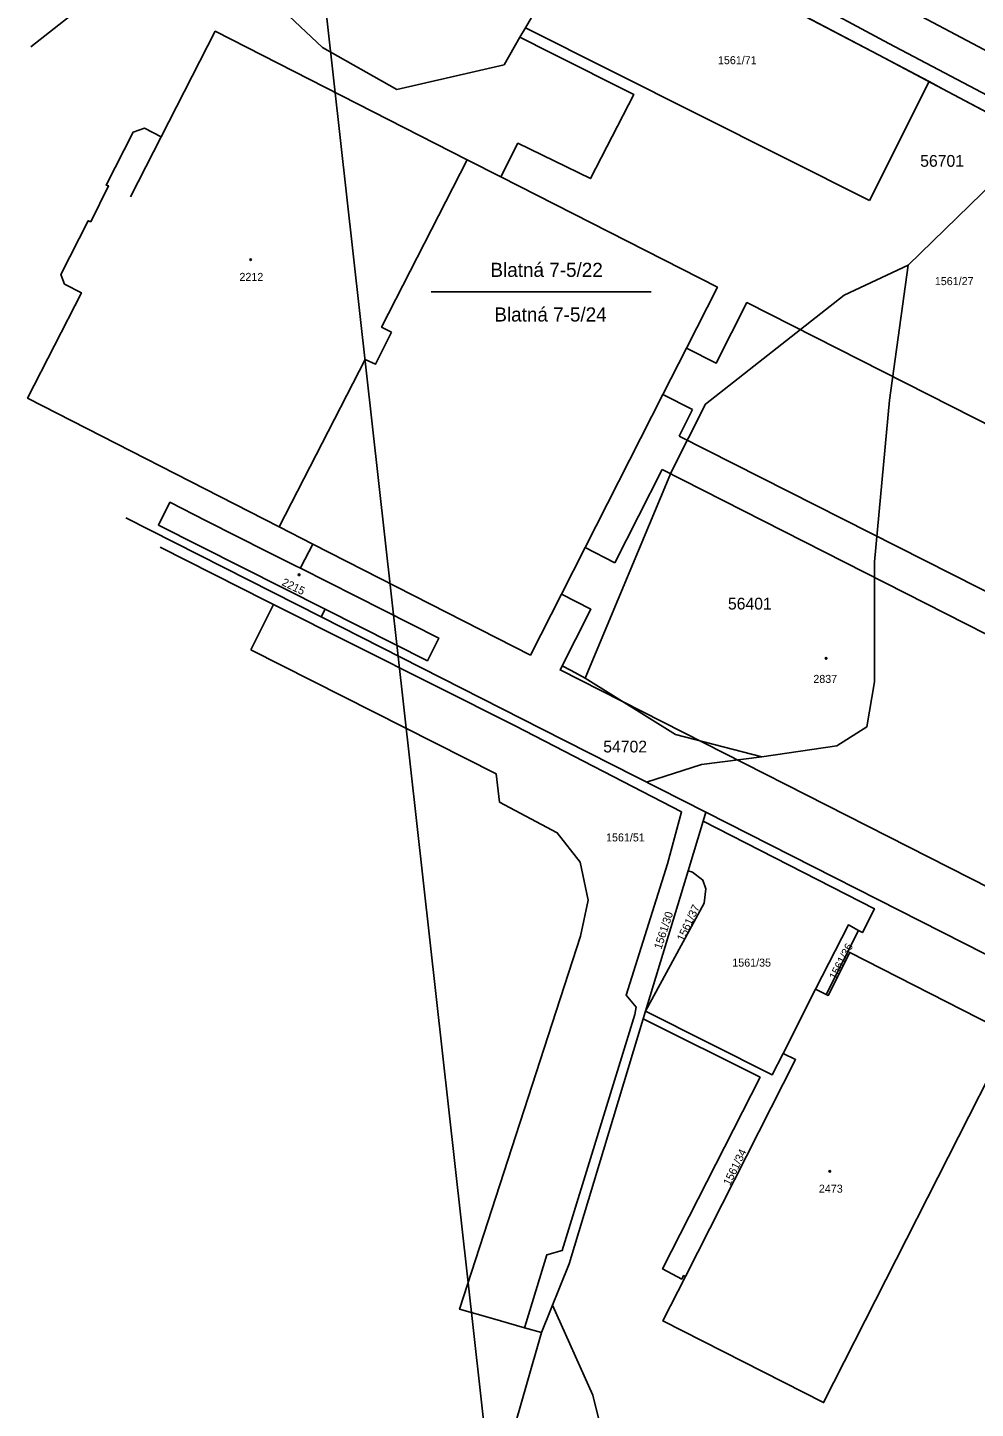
# Model space of a CAD drawing. Extents: x -794765 to -785424, y -1118958 to -1108731.
# Drawn here: x -792861.7 to -792660.4, y -1110737.1 to -1110443.9 of the extents above; entities that cross this region are included whole.
import ezdxf

# ---------------------------------------------------------------- set-up
doc = ezdxf.new("R2010")
doc.units = 0
for name, color, linetype in [('Level 71', 7, 'Continuous'), ('Level 75', 7, 'Continuous'), ('Level 76', 7, 'Continuous'), ('Level 77', 7, 'Continuous'), ('Level 79', 7, 'Continuous'), ('Level 81', 7, 'Continuous'), ('Vrstva 1', 7, 'Continuous')]:
    doc.layers.add(name, color=color, linetype=linetype)

msp = doc.modelspace()

# ---------------------------------------------------------------- linework, layer by layer
at = {"layer": 'Level 71'}
msp.add_lwpolyline([(-792522.06, -1110204.41), (-792422.02, -1111099.6), (-792720.93, -1111133), (-792820.96, -1110237.81)], close=True, dxfattribs=at)
at = {"layer": 'Level 75'}
for p, q in [((-792756.01, -1110443.91), (-792741.07, -1110418.09)), ((-792741.07, -1110418.09), (-792681.03, -1110449.67)), ((-792827.45, -1110421.43), (-792861.09, -1110447.98)), ((-792757.16, -1110445.89), (-792756.01, -1110443.91)), ((-792682.88, -1110480.58), (-792756.01, -1110443.91)), ((-792681.03, -1110449.67), (-792670.27, -1110455.33)), ((-792670.27, -1110455.33), (-792682.88, -1110480.58)), ((-792840.87, -1110547.97), (-792799.39, -1110569.04)), ((-792814.36, -1110576.02), (-792809.5, -1110566.39)), ((-792799.39, -1110569.04), (-792798.52, -1110567.4)), ((-792717.66, -1110610.53), (-792718.24, -1110612.44)), ((-792717.66, -1110610.53), (-792591.1, -1110674.8)), ((-792721.42, -1110622.95), (-792718.24, -1110612.44)), ((-792730.46, -1110652.76), (-792721.42, -1110622.95)), ((-792685.22, -1110635.61), (-792692.14, -1110649.21)), ((-792701.25, -1110661.74), (-792694.38, -1110648.11)), ((-792694.38, -1110648.11), (-792692.14, -1110649.21)), ((-792730.96, -1110654.38), (-792730.46, -1110652.76)), ((-792756.17, -1110720.02), (-792752.56, -1110721.04)), ((-792752.56, -1110721.04), (-792776.5, -1110804.34))]:
    msp.add_line(p, q, dxfattribs=at)
for points in [[(-792827.45, -1110421.43), (-792799.1, -1110448.12), (-792783.32, -1110457.02), (-792760.54, -1110451.74), (-792757.16, -1110445.89)], [(-792761.23, -1110475.55), (-792768.36, -1110471.92), (-792821.87, -1110444.63), (-792833.35, -1110467.07), (-792836.92, -1110465.24), (-792839.29, -1110466.05), (-792845.03, -1110477.35), (-792844.59, -1110477.44), (-792848.33, -1110485.09), (-792848.86, -1110484.89), (-792854.67, -1110496.33), (-792853.9, -1110498.34), (-792850.3, -1110500.18), (-792861.74, -1110522.54), (-792808.28, -1110549.91), (-792801.15, -1110553.55)], [(-792761.23, -1110475.55), (-792757.59, -1110468.44), (-792742.2, -1110475.94), (-792732.96, -1110458.09), (-792750.58, -1110449.21), (-792757.16, -1110445.89)], [(-792617.47, -1110483.28), (-792667.41, -1110456.84), (-792670.27, -1110455.33)], [(-792721.79, -1110511.93), (-792715.21, -1110499), (-792761.23, -1110475.55)], [(-792721.79, -1110511.93), (-792715.49, -1110515.15), (-792708.94, -1110502.27), (-792617.55, -1110548.61), (-792617.98, -1110549.46), (-792615.07, -1110550.92), (-792617.03, -1110554.92), (-792619.99, -1110553.41), (-792631.85, -1110576.75), (-792629.58, -1110577.89), (-792633.4, -1110585.25), (-792635.6, -1110584.14), (-792657.23, -1110626.73), (-792748.62, -1110580.29), (-792742.08, -1110567.4), (-792748.36, -1110564.21)], [(-792748.36, -1110564.21), (-792743.32, -1110554.29), (-792726.81, -1110521.82), (-792721.79, -1110511.93)], [(-792803.79, -1110558.7), (-792804.71, -1110558.23), (-792810.76, -1110555.18), (-792823.8, -1110548.59), (-792831.53, -1110544.69), (-792833.96, -1110549.51), (-792798.52, -1110567.4)], [(-792803.79, -1110558.7), (-792803.68, -1110558.49), (-792801.15, -1110553.55)], [(-792801.15, -1110553.55), (-792754.94, -1110577.15), (-792748.36, -1110564.21)], [(-792833.61, -1110554.24), (-792810.9, -1110565.68), (-792809.5, -1110566.39)], [(-792798.52, -1110567.4), (-792776.83, -1110578.34), (-792774.4, -1110573.53), (-792803.79, -1110558.7)], [(-792809.5, -1110566.39), (-792758.18, -1110592.2), (-792722.84, -1110610.45), (-792725.84, -1110621.49), (-792734.61, -1110649.36), (-792732.48, -1110651.94), (-792732.74, -1110653.49), (-792748.18, -1110703.64), (-792751.42, -1110704.51), (-792755.84, -1110718.93), (-792756.17, -1110720.02)], [(-792799.39, -1110569.04), (-792752.45, -1110592.87), (-792717.66, -1110610.53)], [(-792756.17, -1110720.02), (-792762.96, -1110718.07), (-792769.97, -1110716.07), (-792744.33, -1110636.87), (-792742.66, -1110629.19), (-792744.4, -1110621.12), (-792749.24, -1110614.88), (-792761.47, -1110608.37), (-792762.23, -1110602.33), (-792814.36, -1110576.02)], [(-792718.24, -1110612.44), (-792681.86, -1110631.03), (-792684.41, -1110636.07), (-792685.22, -1110635.61)], [(-792721.42, -1110622.95), (-792720.53, -1110623.24), (-792718.31, -1110624.92), (-792717.67, -1110626.82), (-792718.01, -1110629.81), (-792730.46, -1110652.76)], [(-792694.38, -1110648.11), (-792687.38, -1110634.45), (-792685.22, -1110635.61)], [(-792692.14, -1110649.21), (-792691.69, -1110649.43), (-792687.06, -1110640.34), (-792652.95, -1110657.7), (-792692.66, -1110735.91), (-792726.8, -1110718.56), (-792722.01, -1110709.13)], [(-792701.25, -1110661.74), (-792703.57, -1110666.28), (-792730.46, -1110652.76)], [(-792730.96, -1110654.38), (-792746.73, -1110706.41), (-792752.56, -1110721.04)], [(-792722.01, -1110709.13), (-792722.4, -1110708.94), (-792722.8, -1110709.69), (-792726.88, -1110707.53), (-792706.14, -1110666.79), (-792730.96, -1110654.38)], [(-792722.01, -1110709.13), (-792698.61, -1110663.07), (-792701.25, -1110661.74)]]:
    msp.add_lwpolyline(points, dxfattribs=at)
at = {"layer": 'Level 77'}
for p, q in [((-792707.83, -1110431.64), (-792678.77, -1110447.22)), ((-792643.45, -1110456.57), (-792675.45, -1110439.61)), ((-792678.77, -1110447.22), (-792647.57, -1110463.72)), ((-792833.35, -1110467.07), (-792839.88, -1110479.83)), ((-792726.81, -1110521.82), (-792720.49, -1110525.01)), ((-792720.49, -1110525.01), (-792723.33, -1110530.62)), ((-792723.33, -1110530.62), (-792643.41, -1110571.15)), ((-792737.04, -1110557.56), (-792726.95, -1110537.73)), ((-792726.95, -1110537.73), (-792647.05, -1110578.32)), ((-792743.32, -1110554.29), (-792737.04, -1110557.56))]:
    msp.add_line(p, q, dxfattribs=at)
for points in [[(-792784.44, -1110508.55), (-792786.55, -1110507.47), (-792768.36, -1110471.92)], [(-792808.28, -1110549.91), (-792790.07, -1110514.34), (-792787.84, -1110515.38), (-792784.44, -1110508.55)]]:
    msp.add_lwpolyline(points, dxfattribs=at)
at = {"layer": 'Level 79'}
for centre in [(-792814.37, -1110493.17), (-792804.07, -1110560.09), (-792692.12, -1110577.83), (-792691.35, -1110686.8)]:
    msp.add_circle(centre, 0.175, dxfattribs=at)
at = {"layer": 'Level 81'}
msp.add_line((-792674.7, -1110494.31), (-792647.2, -1110467.54), dxfattribs=at)
for points in [[(-792744.86, -1110416.1), (-792741.07, -1110418.09), (-792681.03, -1110449.67), (-792667.41, -1110456.84), (-792647.2, -1110467.54)], [(-792743.29, -1110582.03), (-792724.95, -1110538.17), (-792717.77, -1110523.81), (-792688.26, -1110500.69), (-792674.7, -1110494.31)], [(-792705.81, -1110598.78), (-792689.86, -1110596.38), (-792683.48, -1110592.4), (-792681.88, -1110582.83), (-792681.88, -1110557.31), (-792678.69, -1110523.02), (-792674.7, -1110494.31)], [(-792748.17, -1110579.41), (-792746.25, -1110580.44), (-792743.29, -1110582.03)], [(-792743.29, -1110582.03), (-792724.15, -1110593.99), (-792705.81, -1110598.78)], [(-792730.28, -1110604.12), (-792730.28, -1110604.12), (-792718.57, -1110600.37), (-792705.81, -1110598.78)], [(-792750.25, -1110715.25), (-792750.25, -1110715.25), (-792741.69, -1110734.35), (-792735.31, -1110759.87), (-792732.12, -1110789.38), (-792735.31, -1110805.33), (-792741.69, -1110809.31), (-792749.67, -1110810.11), (-792776.21, -1110803.33)]]:
    msp.add_lwpolyline(points, dxfattribs=at)
at = {"layer": 'Vrstva 1'}
msp.add_line((-792729.32, -1110500), (-792776.04, -1110500), dxfattribs=at)

# ---------------------------------------------------------------- texts
at = {"layer": 'Level 76'}
for s, p in [('1561/71', (-792715.1, -1110451.63)), ('2212', (-792816.74, -1110497.66)), ('1561/27', (-792669.03, -1110498.56)), ('2837', (-792694.84, -1110583.05)), ('1561/51', (-792738.87, -1110616.72)), ('1561/35', (-792712.05, -1110643.31)), ('2473', (-792693.66, -1110691.32))]:
    msp.add_text(s, height=1.7, dxfattribs=at).set_placement(p)
for s, rotation, p in [('2215', 334, (-792807.9, -1110562.23)), ('1561/30', 72, (-792727.13, -1110639.77)), ('1561/37', 65, (-792722.38, -1110638.09)), ('1561/36', 63, (-792690.07, -1110646.23)), ('1561/34', 64, (-792712.55, -1110689.97))]:
    msp.add_text(s, height=1.7, rotation=rotation, dxfattribs=at).set_placement(p)
at = {"layer": 'Level 81'}
for s, p in [('56701', (-792672.14, -1110473.42)), ('56401', (-792712.98, -1110567.46)), ('54702', (-792739.46, -1110597.82))]:
    msp.add_text(s, height=2.5, dxfattribs=at).set_placement(p)
at = {"layer": 'Vrstva 1'}
for s, p in [('Blatná 7-5/22', (-792763.43, -1110496.81)), ('Blatná 7-5/24', (-792762.6, -1110506.29))]:
    msp.add_text(s, height=3, dxfattribs=at).set_placement(p)

doc.saveas('drawing.dxf')
